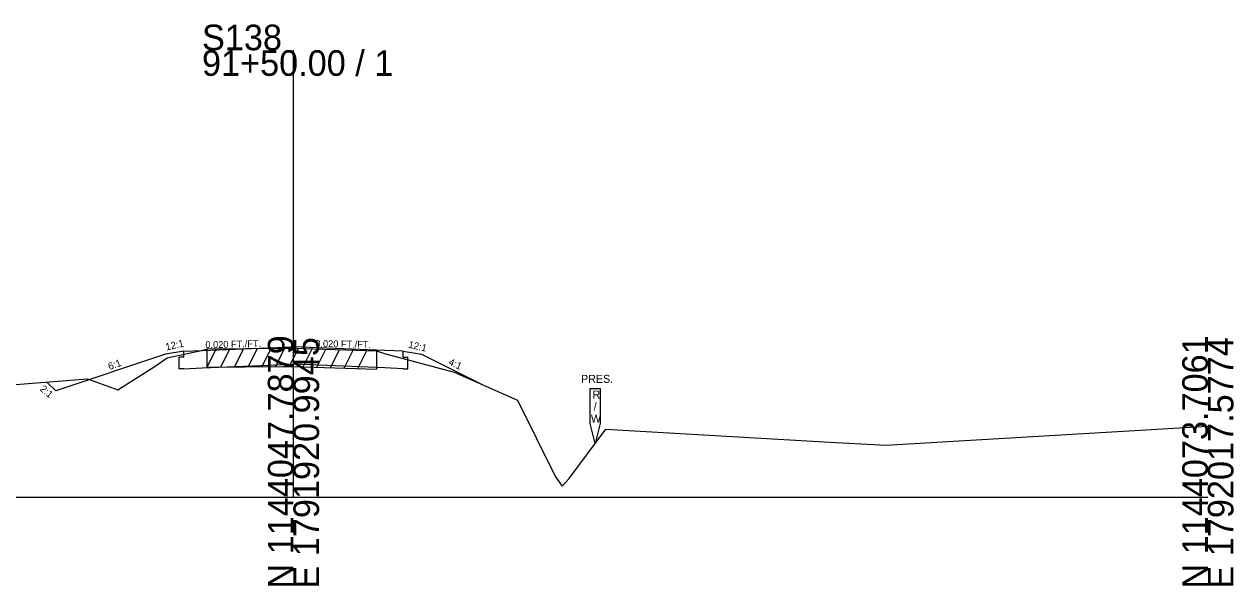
# Model space of a CAD drawing. Extents: x -26 to 1203, y -10 to 19606.
# Drawn here: x 1070.6 to 1202.8, y 2990.3 to 3051.7 of the extents above; entities that cross this region are included whole.
import ezdxf

# ---------------------------------------------------------------- set-up
doc = ezdxf.new("R2010")
doc.units = 0
for name, color, linetype in [('RD_EX_Driveway', 7, 'Continuous'), ('RD_GPK_XS_Cell', 7, 'Continuous'), ('RD_XS_Base', 7, 'Continuous'), ('RD_XS_EarthShd', 7, 'Continuous'), ('RD_XS_ExGround', 7, 'Continuous'), ('RD_XS_ExPaveRet', 7, 'Continuous'), ('RD_XS_ExRW', 7, 'Continuous'), ('RD_XS_Pave', 7, 'Continuous'), ('RD_XS_TX_Slope', 7, 'Continuous')]:
    doc.layers.add(name, color=color, linetype=linetype)

msp = doc.modelspace()

# ---------------------------------------------------------------- linework, layer by layer
at = {"layer": 'RD_GPK_XS_Cell'}
for p, q in [((1100, 3000), (1100, 3048.85)), ((1000, 3000), (1100, 3000)), ((1100, 3000), (1200, 3000))]:
    msp.add_line(p, q, dxfattribs=at)
at = {"layer": 'RD_XS_Base'}
for p, q in [((1088, 3015.31), (1087.5, 3015.29)), ((1087.5, 3014.02), (1087.5, 3015.29)), ((1088, 3015.31), (1088, 3015.94)), ((1112, 3015.31), (1112, 3015.94)), ((1112, 3015.31), (1112.5, 3015.29)), ((1112.5, 3014.02), (1112.5, 3015.29)), ((1088, 3014.04), (1087.5, 3014.02)), ((1088, 3014.04), (1090, 3014.12)), ((1090, 3014.12), (1100, 3014.54)), ((1110, 3014.12), (1100, 3014.54)), ((1112, 3014.04), (1110, 3014.12)), ((1112, 3014.04), (1112.5, 3014.02))]:
    msp.add_line(p, q, dxfattribs=at)
at = {"layer": 'RD_XS_EarthShd'}
for p, q in [((1086, 3015.61), (1074, 3011.61)), ((1088, 3015.94), (1086, 3015.61)), ((1112, 3015.94), (1114, 3015.61)), ((1114, 3015.61), (1120.56, 3012.33)), ((1074, 3011.61), (1073.03, 3012.58))]:
    msp.add_line(p, q, dxfattribs=at)
at = {"layer": 'RD_XS_ExGround'}
msp.add_lwpolyline([(1055.25, 3011.17), (1077.48, 3012.93), (1078.4, 3012.59), (1080.79, 3011.72), (1084.87, 3014.32), (1086.2, 3015.22), (1090.1, 3016.06), (1090.55, 3016.2), (1098.9, 3016.27), (1099.42, 3016.28), (1100, 3016.27), (1109.08, 3016), (1109.96, 3015.69), (1117.58, 3013.65), (1124.5, 3010.58), (1128.66, 3002.23), (1129.4, 3001.19), (1130.17, 3002.04), (1134.16, 3007.41), (1158.05, 3006.06), (1164.78, 3005.69), (1200, 3007.76)], dxfattribs=at)
at = {"layer": 'RD_XS_ExPaveRet'}
for p, q in [((1090.55, 3014.2), (1091.56, 3016.21)), ((1090.55, 3014.2), (1090.55, 3016.2)), ((1092.05, 3014.21), (1093.06, 3016.22)), ((1093.55, 3014.23), (1094.56, 3016.24)), ((1095.05, 3014.24), (1096.06, 3016.25)), ((1096.55, 3014.25), (1097.56, 3016.26)), ((1098.05, 3014.27), (1099.06, 3016.28)), ((1099.55, 3014.28), (1100.54, 3016.25)), ((1101.05, 3014.24), (1102.04, 3016.21)), ((1102.55, 3014.19), (1103.54, 3016.16)), ((1104.05, 3014.15), (1105.04, 3016.12)), ((1105.55, 3014.11), (1106.54, 3016.08)), ((1107.05, 3014.06), (1108.04, 3016.03)), ((1109.08, 3016), (1109.08, 3014)), ((1090.55, 3014.2), (1098.9, 3014.27)), ((1098.9, 3014.27), (1099.42, 3014.28)), ((1099.42, 3014.28), (1100, 3014.27)), ((1100, 3014.27), (1109.08, 3014))]:
    msp.add_line(p, q, dxfattribs=at)
at = {"layer": 'RD_XS_ExRW'}
msp.add_lwpolyline([(1132.45, 3011.86), (1133.55, 3011.86), (1133.55, 3008.03), (1133, 3005.85), (1132.45, 3008.03)], close=True, dxfattribs=at)
at = {"layer": 'RD_XS_Pave'}
for p, q in [((1090, 3016.03), (1100, 3016.44)), ((1110, 3016.03), (1100, 3016.44)), ((1088, 3015.94), (1090, 3016.03)), ((1112, 3015.94), (1110, 3016.03))]:
    msp.add_line(p, q, dxfattribs=at)

# ---------------------------------------------------------------- texts
at = {"layer": 'RD_EX_Driveway'}
msp.add_text('549.13', height=0.0975, rotation=90, dxfattribs=at).set_placement((1100.1, 3016.27))
at = {"layer": 'RD_GPK_XS_Cell'}
for s, p in [('S138', (1090, 3048.85)), ('91+50.00 / 1', (1090, 3046.05))]:
    msp.add_text(s, height=2.8, dxfattribs=at).set_placement(p)
for s, p in [('N 1144047.7879', (1100, 2990)), ('N 1144073.7061', (1200, 2990)), ('E 1791920.9945', (1102.8, 2990)), ('E 1792017.5774', (1202.8, 2990))]:
    msp.add_text(s, height=2.8, rotation=90, dxfattribs=at).set_placement(p)
at = {"layer": 'RD_XS_ExRW'}
for s, p in [('PRES.', (1131.45, 3012.49)), ('R', (1132.71, 3010.77)), ('/', (1132.83, 3009.46)), ('W', (1132.53, 3008.15))]:
    msp.add_text(s, height=0.875, dxfattribs=at).set_placement(p)
at = {"layer": 'RD_XS_TX_Slope'}
for s, height, rotation, p in [('12:1', 0.778, 12.7511, (1086.1, 3016.02)), ('0.020 FT./FT.', 0.7518, 1.1916, (1090.38, 3016.28)), ('0.020 FT./FT.', 0.7518, 358.8084, (1102.39, 3016.43)), ('12:1', 0.778, 347.2489, (1112.51, 3016.34)), ('6:1', 0.778, 19.3982, (1079.89, 3013.89)), ('4:1', 0.778, 335.081, (1116.88, 3014.51)), ('2:1', 0.778, 319.3411, (1072.21, 3011.72))]:
    msp.add_text(s, height=height, rotation=rotation, dxfattribs=at).set_placement(p)

doc.saveas('drawing.dxf')
